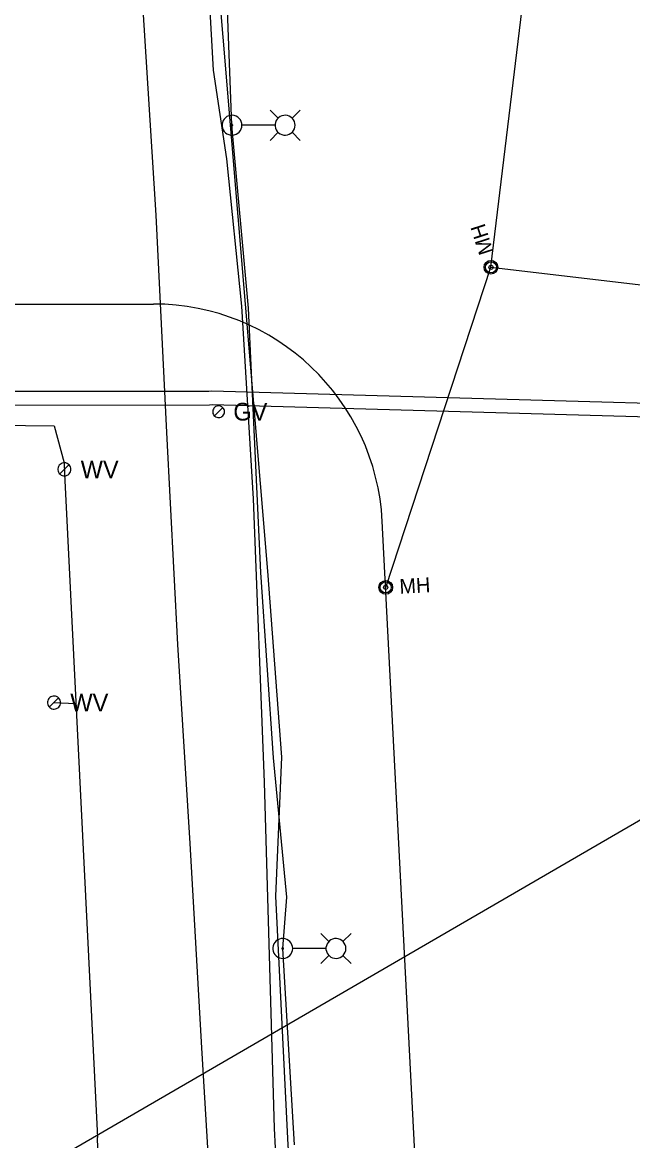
# Model space of a CAD drawing. Extents: x 600849 to 606371, y 330010 to 403088.
# Drawn here: x 604777.9 to 604911.1, y 335171 to 335415.1 of the extents above; entities that cross this region are included whole.
import ezdxf

# ---------------------------------------------------------------- set-up
doc = ezdxf.new("R2010")
doc.units = 0
for name, color, linetype in [('E_FTMS_Conduit', 7, 'Continuous'), ('E_LTG', 7, 'Continuous'), ('E_LTG_CID', 7, 'Continuous'), ('E_UTL_E_UG', 7, 'Continuous'), ('E_UTL_FO_UG_QWEST', 7, 'Continuous'), ('E_UTL_G', 7, 'Continuous'), ('E_UTL_G_UG', 7, 'Continuous'), ('E_UTL_Overhead', 7, 'Continuous'), ('E_UTL_SAN_MH', 7, 'Continuous'), ('E_UTL_SAN_UG', 7, 'Continuous'), ('E_UTL_SAN_UG_MMSD', 7, 'Continuous'), ('E_UTL_W', 7, 'Continuous'), ('E_UTL_W_UG', 7, 'Continuous')]:
    doc.layers.add(name, color=color, linetype=linetype)

msp = doc.modelspace()

# ---------------------------------------------------------------- linework, layer by layer
at = {"layer": 'E_FTMS_Conduit'}
msp.add_lwpolyline([(604865.66, 334623.82), (604860.3, 334662.92), (604859.68, 334742.73), (604857.4, 334780.45), (604853.68, 334856.29), (604850.24, 334895.79), (604847.27, 334936.94), (604845.54, 335011.51), (604843.22, 335054.36), (604842.26, 335092.55), (604835.93, 335170.05), (604833.24, 335224.35), (604834.53, 335254.76), (604831.45, 335295.34), (604820.14, 335431.05), (604817.01, 335471.26), (604813.1, 335515.04), (604806.53, 335560.93), (604800.96, 335611.56)], dxfattribs=at)
at = {"layer": 'E_LTG'}
for points in [[(604825.82, 335392.65), (604825.78, 335393.06), (604825.66, 335393.46), (604825.47, 335393.83), (604825.21, 335394.15), (604824.9, 335394.42), (604824.54, 335394.63), (604824.15, 335394.76), (604823.74, 335394.82), (604823.33, 335394.8), (604822.93, 335394.71), (604822.55, 335394.53), (604822.22, 335394.29), (604821.93, 335393.99), (604821.71, 335393.65), (604821.55, 335393.26), (604821.47, 335392.86), (604821.47, 335392.44), (604821.55, 335392.04), (604821.71, 335391.65), (604821.93, 335391.3), (604822.22, 335391), (604822.55, 335390.76), (604822.93, 335390.59), (604823.33, 335390.5), (604823.74, 335390.48), (604824.15, 335390.53), (604824.54, 335390.67), (604824.9, 335390.88), (604825.21, 335391.15), (604825.47, 335391.47), (604825.66, 335391.84), (604825.78, 335392.24), (604825.82, 335392.65)], [(604833.72, 335394.17), (604831.94, 335395.95)], [(604837.42, 335392.65), (604837.38, 335393.06), (604837.26, 335393.46), (604837.07, 335393.83), (604836.82, 335394.15), (604836.51, 335394.42), (604836.15, 335394.63), (604835.76, 335394.76), (604835.35, 335394.82), (604834.93, 335394.8), (604834.53, 335394.71), (604834.16, 335394.53), (604833.82, 335394.29), (604833.53, 335393.99), (604833.31, 335393.65), (604833.16, 335393.26), (604833.08, 335392.86), (604833.08, 335392.44), (604833.16, 335392.04), (604833.31, 335391.65), (604833.53, 335391.3), (604833.82, 335391), (604834.16, 335390.76), (604834.53, 335390.59), (604834.93, 335390.5), (604835.35, 335390.48), (604835.76, 335390.53), (604836.15, 335390.67), (604836.51, 335390.88), (604836.82, 335391.15), (604837.07, 335391.47), (604837.26, 335391.84), (604837.38, 335392.24), (604837.42, 335392.65)], [(604836.77, 335394.17), (604838.55, 335395.95)], [(604823.81, 335392.65), (604823.8, 335392.68), (604823.79, 335392.71), (604823.78, 335392.74), (604823.76, 335392.76), (604823.74, 335392.78), (604823.71, 335392.8), (604823.68, 335392.81), (604823.65, 335392.82), (604823.62, 335392.81), (604823.59, 335392.81), (604823.56, 335392.79), (604823.53, 335392.77), (604823.51, 335392.75), (604823.49, 335392.73), (604823.48, 335392.7), (604823.47, 335392.66), (604823.47, 335392.63), (604823.48, 335392.6), (604823.49, 335392.57), (604823.51, 335392.55), (604823.53, 335392.52), (604823.56, 335392.51), (604823.59, 335392.49), (604823.62, 335392.48), (604823.65, 335392.48), (604823.68, 335392.49), (604823.71, 335392.5), (604823.74, 335392.51), (604823.76, 335392.53), (604823.78, 335392.56), (604823.79, 335392.59), (604823.8, 335392.62), (604823.81, 335392.65)], [(604833.03, 335392.65), (604825.85, 335392.65)], [(604833.72, 335391.13), (604831.94, 335389.35)], [(604836.77, 335391.13), (604838.55, 335389.35)], [(604836.89, 335212.97), (604836.85, 335213.38), (604836.73, 335213.78), (604836.54, 335214.15), (604836.28, 335214.47), (604835.97, 335214.74), (604835.61, 335214.95), (604835.22, 335215.08), (604834.81, 335215.14), (604834.4, 335215.12), (604834, 335215.03), (604833.62, 335214.85), (604833.29, 335214.61), (604833, 335214.31), (604832.78, 335213.97), (604832.62, 335213.58), (604832.54, 335213.18), (604832.54, 335212.76), (604832.62, 335212.36), (604832.78, 335211.97), (604833, 335211.62), (604833.29, 335211.33), (604833.62, 335211.09), (604834, 335210.91), (604834.4, 335210.82), (604834.81, 335210.8), (604835.22, 335210.86), (604835.61, 335210.99), (604835.97, 335211.2), (604836.28, 335211.47), (604836.54, 335211.79), (604836.73, 335212.16), (604836.85, 335212.56), (604836.89, 335212.97)], [(604844.79, 335214.49), (604843.01, 335216.27)], [(604848.49, 335212.97), (604848.45, 335213.38), (604848.33, 335213.78), (604848.14, 335214.15), (604847.89, 335214.47), (604847.58, 335214.74), (604847.22, 335214.95), (604846.83, 335215.08), (604846.42, 335215.14), (604846, 335215.12), (604845.6, 335215.03), (604845.23, 335214.85), (604844.89, 335214.61), (604844.6, 335214.31), (604844.38, 335213.97), (604844.23, 335213.58), (604844.15, 335213.18), (604844.15, 335212.76), (604844.23, 335212.36), (604844.38, 335211.97), (604844.6, 335211.62), (604844.89, 335211.33), (604845.23, 335211.09), (604845.6, 335210.91), (604846, 335210.82), (604846.42, 335210.8), (604846.83, 335210.86), (604847.22, 335210.99), (604847.58, 335211.2), (604847.89, 335211.47), (604848.14, 335211.79), (604848.33, 335212.16), (604848.45, 335212.56), (604848.49, 335212.97)], [(604847.84, 335214.49), (604849.62, 335216.27)], [(604834.88, 335212.97), (604834.87, 335213), (604834.86, 335213.03), (604834.85, 335213.06), (604834.83, 335213.08), (604834.81, 335213.11), (604834.78, 335213.12), (604834.75, 335213.13), (604834.72, 335213.14), (604834.69, 335213.13), (604834.66, 335213.13), (604834.63, 335213.11), (604834.6, 335213.1), (604834.58, 335213.07), (604834.56, 335213.05), (604834.55, 335213.02), (604834.54, 335212.99), (604834.54, 335212.95), (604834.55, 335212.92), (604834.56, 335212.89), (604834.58, 335212.87), (604834.6, 335212.84), (604834.63, 335212.83), (604834.66, 335212.81), (604834.69, 335212.8), (604834.72, 335212.8), (604834.75, 335212.81), (604834.78, 335212.82), (604834.81, 335212.83), (604834.83, 335212.85), (604834.85, 335212.88), (604834.86, 335212.91), (604834.87, 335212.94), (604834.88, 335212.97)], [(604844.1, 335212.97), (604836.92, 335212.97)], [(604844.79, 335211.45), (604843.01, 335209.67)], [(604847.84, 335211.45), (604849.62, 335209.67)]]:
    msp.add_lwpolyline(points, dxfattribs=at)
at = {"layer": 'E_LTG_CID'}
msp.add_lwpolyline([(604837.28, 335170.14), (604834.71, 335212.97), (604835.59, 335224.17), (604832.71, 335254.61), (604829.93, 335295), (604827.26, 335352.71), (604823.64, 335392.65), (604822.12, 335431.36), (604818.86, 335471.26), (604814.5, 335515.53), (604809.84, 335560.94), (604807.57, 335571.71), (604804.68, 335594.13)], dxfattribs=at)
at = {"layer": 'E_UTL_E_UG'}
msp.add_lwpolyline([(604841.27, 334614.96), (604838.91, 334672.58), (604835.72, 334731.86), (604833.33, 334793.2), (604830.28, 334854.41), (604827.22, 334896.47), (604825.25, 334968.56), (604825.04, 334973.69), (604824.51, 334978.47), (604823.31, 335011.26), (604820.86, 335070.81), (604819.86, 335112.84), (604819.04, 335158.63), (604817.07, 335191.32), (604814.49, 335235.91), (604811.85, 335279.29), (604809.46, 335325.61), (604807.12, 335373), (604804.05, 335421.46), (604799.37, 335470.45), (604793.24, 335522.54), (604789.06, 335554.45), (604783.73, 335590.4)], dxfattribs=at)
at = {"layer": 'E_UTL_FO_UG_QWEST'}
msp.add_lwpolyline([(604880.24, 334183.25), (604876.98, 334256.9), (604873.2, 334330.88), (604873.06, 334361.71), (604869.66, 334408.48), (604865.91, 334483.81), (604863.36, 334557.53), (604860.02, 334633.27), (604855.03, 334705.91), (604850.49, 334782.01), (604846.38, 334856.9), (604842.05, 334937.04), (604840.43, 335012.73), (604837.31, 335089.26), (604832.93, 335173.7), (604830.71, 335249.27), (604828.33, 335311.14), (604825.79, 335353.18), (604822.55, 335385.33), (604819.59, 335404.65), (604816.19, 335465.69), (604807.94, 335539.85), (604801.77, 335593.87)], dxfattribs=at)
at = {"layer": 'E_UTL_G'}
for points in [[(604822, 335330.12), (604821.98, 335330.36), (604821.91, 335330.6), (604821.8, 335330.81), (604821.65, 335331), (604821.46, 335331.16), (604821.25, 335331.29), (604821.02, 335331.37), (604820.78, 335331.4), (604820.54, 335331.39), (604820.3, 335331.33), (604820.08, 335331.23), (604819.88, 335331.09), (604819.71, 335330.91), (604819.58, 335330.71), (604819.49, 335330.48), (604819.44, 335330.24), (604819.44, 335330), (604819.49, 335329.76), (604819.58, 335329.53), (604819.71, 335329.33), (604819.88, 335329.15), (604820.08, 335329.01), (604820.3, 335328.91), (604820.54, 335328.85), (604820.78, 335328.84), (604821.02, 335328.87), (604821.25, 335328.95), (604821.46, 335329.07), (604821.65, 335329.23), (604821.8, 335329.43), (604821.91, 335329.64), (604821.98, 335329.88), (604822, 335330.12)], [(604819.81, 335329.21), (604821.63, 335331.03)]]:
    msp.add_lwpolyline(points, dxfattribs=at)
at = {"layer": 'E_UTL_G_UG'}
for points in [[(604736.18, 335331.82), (604751.98, 335334.58), (604818.56, 335334.64), (604819.25, 335334.71), (604999.69, 335329.61)], [(604751.98, 335331.58), (604818.7, 335331.64), (604819.34, 335331.7), (604992.05, 335326.83)], [(604751.98, 335331.58), (604818.7, 335331.64), (604819.34, 335331.7), (604992.05, 335326.83)]]:
    msp.add_lwpolyline(points, dxfattribs=at)
at = {"layer": 'E_UTL_Overhead'}
msp.add_lwpolyline([(604782.82, 335165.57), (605004.43, 335294.31)], dxfattribs=at)
at = {"layer": 'E_UTL_SAN_MH'}
for centre, radius in [((604880.14, 335361.64), 1.5), ((604880.14, 335361.64), 1.2), ((604880.14, 335361.64), 0.45), ((604857.18, 335291.79), 1.5), ((604857.18, 335291.79), 1.2), ((604857.18, 335291.79), 0.45)]:
    msp.add_circle(centre, radius, dxfattribs=at)
at = {"layer": 'E_UTL_SAN_UG'}
for p, q in [((604880.14, 335361.64), (604909.37, 335602.98)), ((604857.19, 335291.76), (604880.14, 335361.64)), ((604880.14, 335361.64), (605021.69, 335345.12))]:
    msp.add_line(p, q, dxfattribs=at)
at = {"layer": 'E_UTL_SAN_UG_MMSD'}
for p, q in [((604129.05, 335353.62), (604806.5, 335353.62)), ((604889.58, 334663.41), (604856.43, 335306.2))]:
    msp.add_line(p, q, dxfattribs=at)
msp.add_arc((604806.5, 335303.62), 50, 2.9523, 90, dxfattribs=at)
at = {"layer": 'E_UTL_W'}
for points in [[(604788.49, 335317.54), (604788.46, 335317.81), (604788.38, 335318.07), (604788.26, 335318.31), (604788.09, 335318.52), (604787.89, 335318.7), (604787.65, 335318.84), (604787.4, 335318.93), (604787.13, 335318.96), (604786.86, 335318.95), (604786.59, 335318.89), (604786.35, 335318.77), (604786.13, 335318.62), (604785.94, 335318.42), (604785.79, 335318.19), (604785.69, 335317.94), (604785.64, 335317.68), (604785.64, 335317.4), (604785.69, 335317.14), (604785.79, 335316.89), (604785.94, 335316.66), (604786.13, 335316.46), (604786.35, 335316.3), (604786.59, 335316.19), (604786.86, 335316.13), (604787.13, 335316.12), (604787.4, 335316.15), (604787.65, 335316.24), (604787.89, 335316.38), (604788.09, 335316.56), (604788.26, 335316.77), (604788.38, 335317.01), (604788.46, 335317.27), (604788.49, 335317.54)], [(604786.05, 335316.53), (604788.07, 335318.55)], [(604786.23, 335266.63), (604786.2, 335266.9), (604786.12, 335267.16), (604786, 335267.4), (604785.83, 335267.61), (604785.63, 335267.79), (604785.39, 335267.93), (604785.14, 335268.02), (604784.87, 335268.05), (604784.6, 335268.04), (604784.33, 335267.98), (604784.09, 335267.86), (604783.87, 335267.71), (604783.68, 335267.51), (604783.53, 335267.28), (604783.43, 335267.03), (604783.38, 335266.77), (604783.38, 335266.49), (604783.43, 335266.23), (604783.53, 335265.98), (604783.68, 335265.75), (604783.87, 335265.55), (604784.09, 335265.39), (604784.33, 335265.28), (604784.6, 335265.22), (604784.87, 335265.21), (604785.14, 335265.24), (604785.39, 335265.33), (604785.63, 335265.47), (604785.83, 335265.65), (604786, 335265.86), (604786.12, 335266.1), (604786.2, 335266.36), (604786.23, 335266.63)], [(604783.79, 335265.62), (604785.81, 335267.64)]]:
    msp.add_lwpolyline(points, dxfattribs=at)
at = {"layer": 'E_UTL_W_UG'}
msp.add_line((604787.1, 335316.54), (604794.29, 335171.74), dxfattribs=at)
for points in [[(604766, 335327.28), (604784.88, 335327.05), (604787.01, 335318.97)], [(604787.01, 335318.97), (604787.1, 335316.54)], [(604784.8, 335266.63), (604789.59, 335266.44)], [(604797.31, 335097.75), (604796.29, 335115.98), (604795.35, 335137.98), (604794.29, 335171.74)]]:
    msp.add_lwpolyline(points, dxfattribs=at)

# ---------------------------------------------------------------- texts
at = {"layer": 'E_UTL_G'}
msp.add_text('GV', height=3.85, dxfattribs=at).set_placement((604823.93, 335328.19))
at = {"layer": 'E_UTL_SAN_MH'}
for rotation, p in [(107.8614, (604880.76, 335365)), (3.3276, (604860.27, 335290.35))]:
    msp.add_text('MH', height=3.24, rotation=rotation, dxfattribs=at).set_placement(p)
at = {"layer": 'E_UTL_W'}
for p in [(604790.63, 335315.61), (604788.37, 335264.7)]:
    msp.add_text('WV', height=3.85, dxfattribs=at).set_placement(p)

doc.saveas('drawing.dxf')
